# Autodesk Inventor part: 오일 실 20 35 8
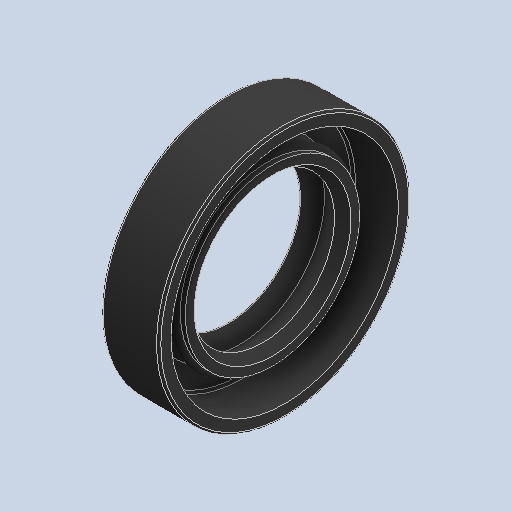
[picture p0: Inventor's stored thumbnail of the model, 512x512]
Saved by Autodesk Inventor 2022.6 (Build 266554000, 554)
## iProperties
Created: 2024-09
Part Number: 오일 실 20 35 8
Material: 고무
Description: 오일-실
Document SubType Name: Modeling
Designer: Class 001
Density: 0.93 g/cm^3
Appearance: 기본값
Author: jhkim
Sending System: Autodesk Inventor 2025
Preprocessor: ST-DEVELOPER v20
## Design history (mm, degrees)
feature "Solid1"
node "솔리드1"
